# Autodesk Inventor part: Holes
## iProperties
Shininess: 65.0
Angle Display Precision: 2
Document Length Units: 11269
Document Angle Units: 11279
Document Time Units: 11290
Document Mass Units: 11283
Document Length Units Precision: 3
Document Angle Units Precision: 2
Created: 2001-11
Part Number: Holes
Document SubType Name: Modeling
Designer: Renu Muthoo
Density: 1 g/cm^3
Density: 0.0
Volumn: 0.0
Area: 0.0
PropertySet Name: Model Information
Control State: 0
Master: False
Checked Out: False
Author: Renu Muthoo
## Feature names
1. Extrusion1
2. Hole3
